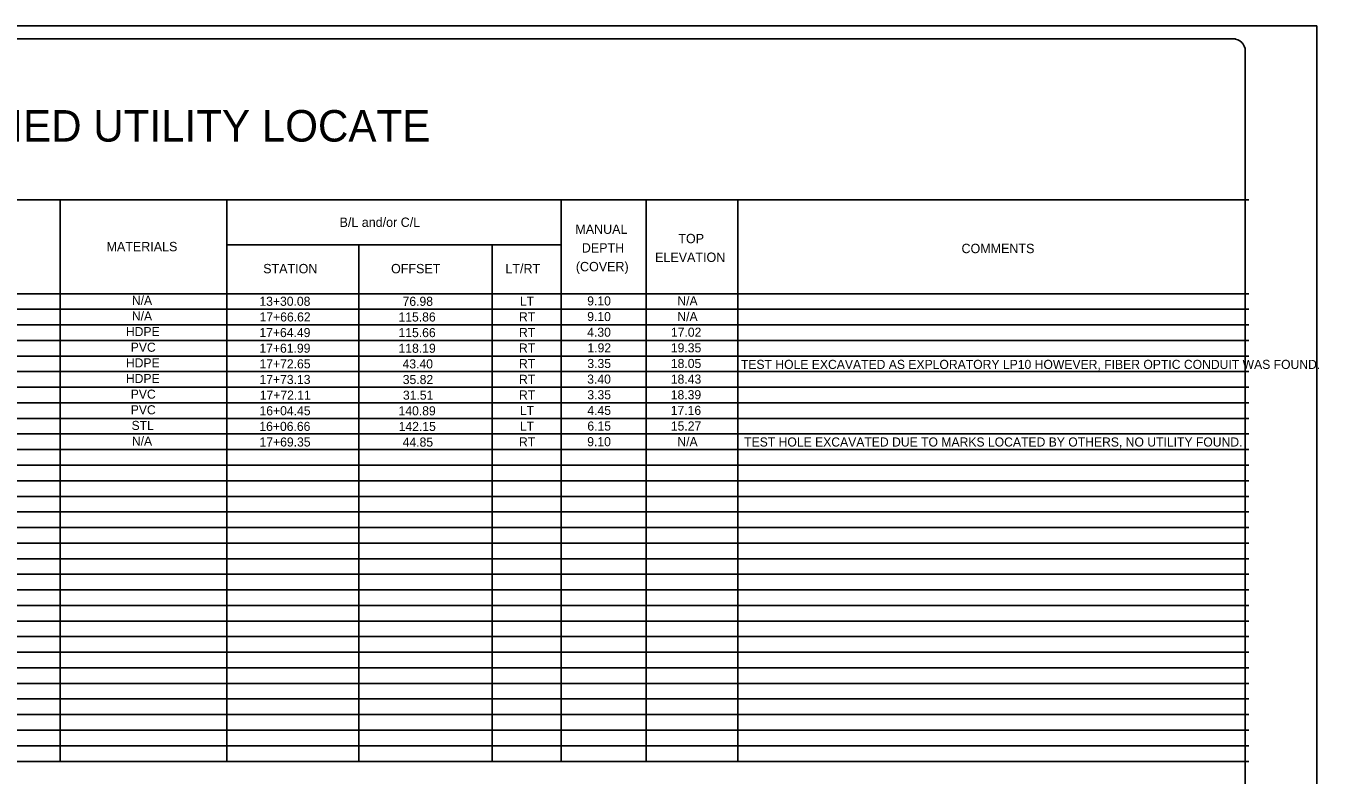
# Model space of a CAD drawing. Extents: x -769.4 to -731.2, y -2181.6 to -2171.
# Drawn here: x -762.64 to -752.68, y -2176.75 to -2170.98 of the extents above; entities that cross this region are included whole.
import ezdxf

# ---------------------------------------------------------------- set-up
doc = ezdxf.new("R2010")
doc.units = 0
for name, color, linetype in [('Default', 7, 'Continuous'), ('PlotBorder_dp', 7, 'Continuous'), ('TextSurveyLabel', 7, 'Continuous')]:
    doc.layers.add(name, color=color, linetype=linetype)

msp = doc.modelspace()

# ---------------------------------------------------------------- linework, layer by layer
at = {"layer": 'Default'}
for p, q in [((-753.3255, -2171.0816), (-768.5566, -2171.0816)), ((-753.2501, -2181.2948), (-753.2501, -2171.175))]:
    msp.add_line(p, q, dxfattribs=at)
msp.add_ellipse((-753.3436, -2171.1751), major_axis=(0, 0.0935), ratio=0.999927, start_param=4.712389, end_param=6.283185, dxfattribs=at)
at = {"layer": 'PlotBorder_dp'}
msp.add_lwpolyline([(-769.2001, -2181.5815), (-752.7001, -2181.5815), (-752.7001, -2170.9815), (-769.2001, -2170.9815)], close=True, dxfattribs=at)
at = {"layer": 'TextSurveyLabel'}
for p, q in [((-768.6228, -2172.3204), (-753.2228, -2172.3204)), ((-768.5828, -2172.3204), (-753.2228, -2172.3204)), ((-762.3784, -2172.3204), (-762.3784, -2176.6428)), ((-761.0943, -2172.3204), (-761.0943, -2176.6428)), ((-758.5202, -2172.3204), (-758.5202, -2176.6428)), ((-757.8659, -2172.3204), (-757.8659, -2176.6428)), ((-757.1595, -2172.3215), (-757.1595, -2176.6428)), ((-761.0943, -2172.6679), (-758.5202, -2172.6679)), ((-760.0781, -2172.6679), (-760.0781, -2176.6428)), ((-759.0501, -2172.6679), (-759.0501, -2176.6428)), ((-768.6228, -2173.0428), (-753.2228, -2173.0428)), ((-768.6228, -2173.163), (-753.2228, -2173.163)), ((-768.6228, -2173.2828), (-753.2228, -2173.2828)), ((-768.6228, -2173.4027), (-753.2228, -2173.4027)), ((-768.6228, -2173.5228), (-753.2228, -2173.5228)), ((-768.6228, -2173.643), (-753.2228, -2173.643)), ((-768.6228, -2173.7628), (-753.2228, -2173.7628)), ((-768.6228, -2173.8827), (-753.2228, -2173.8827)), ((-768.6228, -2174.0028), (-753.2228, -2174.0028)), ((-768.6228, -2174.123), (-753.2228, -2174.123)), ((-768.6228, -2174.2428), (-753.2228, -2174.2428)), ((-768.6228, -2174.3627), (-753.2228, -2174.3627)), ((-768.6228, -2174.4828), (-753.2228, -2174.4828)), ((-768.6228, -2174.603), (-753.2228, -2174.603)), ((-768.6228, -2174.7228), (-753.2228, -2174.7228)), ((-768.6228, -2174.843), (-753.2228, -2174.843)), ((-768.6228, -2174.9628), (-753.2228, -2174.9628)), ((-768.6228, -2175.0827), (-753.2228, -2175.0827)), ((-768.6228, -2175.2028), (-753.2228, -2175.2028)), ((-768.6228, -2175.323), (-753.2228, -2175.323)), ((-768.6228, -2175.4428), (-753.2228, -2175.4428)), ((-768.6228, -2175.5627), (-753.2228, -2175.5627)), ((-768.6228, -2175.6828), (-753.2228, -2175.6828)), ((-768.6228, -2175.803), (-753.2228, -2175.803)), ((-768.6228, -2175.9228), (-753.2228, -2175.9228)), ((-768.6228, -2176.0427), (-753.2228, -2176.0427)), ((-768.6228, -2176.1628), (-753.2228, -2176.1628)), ((-768.6228, -2176.283), (-753.2228, -2176.283)), ((-768.6228, -2176.4028), (-753.2228, -2176.4028)), ((-768.6228, -2176.523), (-753.2228, -2176.523)), ((-768.6228, -2176.6428), (-753.2228, -2176.6428))]:
    msp.add_line(p, q, dxfattribs=at)

# ---------------------------------------------------------------- texts
for s, height, p in [('   VERIFIED UTILITY LOCATE   ', 0.242647, (-763.981, -2171.8723)), ('B/L and/or C/L', 0.072, (-760.2269, -2172.5289)), ('MANUAL ', 0.072, (-758.4106, -2172.5824)), ('TOP', 0.072, (-757.6172, -2172.6544)), ('MATERIALS', 0.072, (-762.0218, -2172.7162)), ('DEPTH ', 0.072, (-758.3607, -2172.7264)), ('ELEVATION', 0.072, (-757.7962, -2172.7984)), ('COMMENTS', 0.072, (-755.4359, -2172.7309)), ('STATION', 0.072, (-760.815, -2172.8859)), ('OFFSET', 0.072, (-759.83, -2172.8859)), ('LT/RT', 0.072, (-758.9492, -2172.8859)), ('(COVER)', 0.072, (-758.4065, -2172.8704)), ('N/A', 0.07, (-761.8268, -2173.1289)), ('13+30.08', 0.07, (-760.8443, -2173.1364)), ('76.98', 0.07, (-759.7414, -2173.1367)), ('LT', 0.07, (-758.8379, -2173.1351)), ('9.10', 0.07, (-758.3191, -2173.1336)), ('N/A', 0.07, (-757.6247, -2173.1335)), ('N/A', 0.07, (-761.8268, -2173.2493)), ('17+66.62', 0.07, (-760.8428, -2173.2568)), ('115.86', 0.07, (-759.7727, -2173.2571)), ('RT', 0.07, (-758.8446, -2173.2555)), ('9.10', 0.07, (-758.3191, -2173.254)), ('N/A', 0.07, (-757.6247, -2173.2539)), ('HDPE', 0.07, (-761.8728, -2173.3697)), ('17+64.49', 0.07, (-760.8443, -2173.3772)), ('115.66', 0.07, (-759.7727, -2173.3775)), ('RT', 0.07, (-758.8446, -2173.3759)), ('4.30', 0.07, (-758.3191, -2173.3744)), ('17.02', 0.07, (-757.6741, -2173.3743)), ('PVC', 0.07, (-761.8356, -2173.4901)), ('1.92', 0.07, (-758.3174, -2173.4948)), ('19.35', 0.07, (-757.6748, -2173.4947)), ('17+61.99', 0.07, (-760.8443, -2173.4975)), ('118.19', 0.07, (-759.7724, -2173.4979)), ('RT', 0.07, (-758.8446, -2173.4963)), ('HDPE', 0.07, (-761.8728, -2173.6105)), ('17+72.65', 0.07, (-760.8434, -2173.6179)), ('43.40', 0.07, (-759.7415, -2173.6183)), ('RT', 0.07, (-758.8446, -2173.6167)), ('3.35', 0.07, (-758.318, -2173.6152)), ('18.05', 0.07, (-757.6748, -2173.6151)), ('TEST HOLE EXCAVATED AS EXPLORATORY LP10 HOWEVER, FIBER OPTIC CONDUIT WAS FOUND.', 0.07, (-757.1353, -2173.6222)), ('HDPE', 0.07, (-761.8728, -2173.7309)), ('17+73.13', 0.07, (-760.8438, -2173.7382)), ('35.82', 0.07, (-759.7399, -2173.7387)), ('RT', 0.07, (-758.8446, -2173.7371)), ('3.40', 0.07, (-758.3191, -2173.7356)), ('18.43', 0.07, (-757.6751, -2173.7355)), ('PVC', 0.07, (-761.8356, -2173.8513)), ('17+72.11', 0.07, (-760.8415, -2173.8586)), ('31.51', 0.07, (-759.7386, -2173.8591)), ('RT', 0.07, (-758.8446, -2173.8575)), ('3.35', 0.07, (-758.318, -2173.856)), ('18.39', 0.07, (-757.6756, -2173.8559)), ('PVC', 0.07, (-761.8356, -2173.9717)), ('16+04.45', 0.07, (-760.8434, -2173.9789)), ('140.89', 0.07, (-759.7724, -2173.9795)), ('LT', 0.07, (-758.8379, -2173.9779)), ('4.45', 0.07, (-758.318, -2173.9764)), ('17.16', 0.07, (-757.6759, -2173.9763)), ('STL', 0.07, (-761.8291, -2174.0921)), ('16+06.66', 0.07, (-760.8446, -2174.0993)), ('142.15', 0.07, (-759.7715, -2174.0999)), ('LT', 0.07, (-758.8379, -2174.0983)), ('6.15', 0.07, (-758.318, -2174.0968)), ('15.27', 0.07, (-757.6749, -2174.0967)), ('N/A', 0.07, (-761.8268, -2174.2125)), ('17+69.35', 0.07, (-760.8434, -2174.2196)), ('44.85', 0.07, (-759.7405, -2174.2203)), ('RT', 0.07, (-758.8446, -2174.2187)), ('9.10', 0.07, (-758.3191, -2174.2172)), ('N/A', 0.07, (-757.6247, -2174.2171)), ('TEST HOLE EXCAVATED DUE TO MARKS LOCATED BY OTHERS, NO UTILITY FOUND.', 0.07, (-757.11, -2174.2196))]:
    msp.add_text(s, height=height, dxfattribs=at).set_placement(p)

doc.saveas('drawing.dxf')
